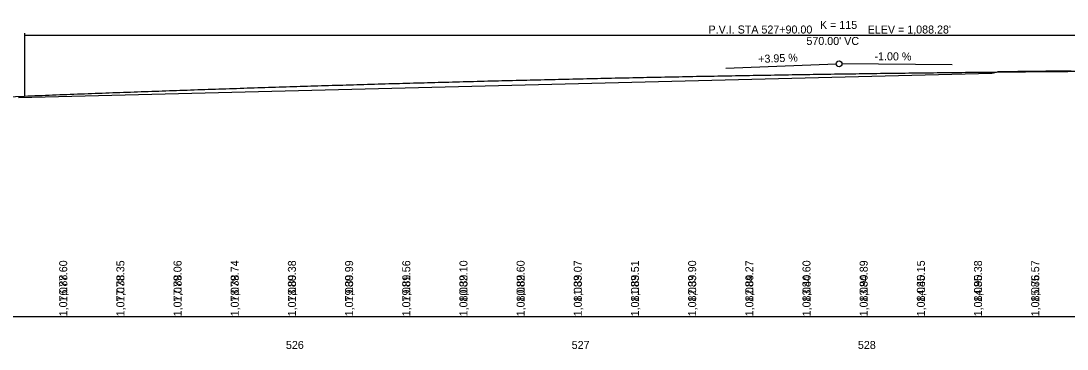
# Model space of a CAD drawing. Extents: x 2241514 to 2245530, y 509521 to 510188.
# Drawn here: x 2242780.9 to 2243146.9, y 509759.6 to 509874.3 of the extents above; entities that cross this region are included whole.
import ezdxf

# ---------------------------------------------------------------- set-up
doc = ezdxf.new("R2010")
doc.units = 0
for name, color, linetype in [('GK_Cells', 7, 'Continuous'), ('PF_P_Grade_Line', 7, 'Continuous'), ('PF_P_Sta_Elev_Text', 7, 'Continuous'), ('PF_P_Text', 7, 'Continuous'), ('PF_X_Ground_Line', 7, 'Continuous'), ('PF_X_Text', 7, 'Continuous')]:
    doc.layers.add(name, color=color, linetype=linetype)

msp = doc.modelspace()

# ---------------------------------------------------------------- linework, layer by layer
at = {"layer": 'GK_Cells'}
msp.add_line((2241529.6, 509771.03), (2245529.6, 509771.03), dxfattribs=at)
at = {"layer": 'PF_P_Grade_Line'}
msp.add_line((2242718.21, 509845.53), (2242782.14, 509848.05), dxfattribs=at)
msp.add_spline([(2242782.14, 509848.05), (2242792.04, 509848.44), (2242801.94, 509848.82), (2242811.84, 509849.19), (2242821.74, 509849.55), (2242831.64, 509849.9), (2242841.54, 509850.25), (2242851.44, 509850.58), (2242861.34, 509850.91), (2242871.24, 509851.23), (2242881.14, 509851.54), (2242891.04, 509851.84), (2242900.94, 509852.13), (2242910.84, 509852.42), (2242920.74, 509852.69), (2242930.64, 509852.96), (2242940.54, 509853.22), (2242950.44, 509853.47), (2242960.34, 509853.71), (2242970.24, 509853.95), (2242980.14, 509854.17), (2242990.04, 509854.39), (2242999.94, 509854.6), (2243009.84, 509854.8), (2243019.74, 509854.99), (2243029.64, 509855.17), (2243039.54, 509855.34), (2243049.44, 509855.51), (2243059.34, 509855.67), (2243069.24, 509855.82), (2243079.14, 509855.96), (2243089.04, 509856.09), (2243098.94, 509856.21), (2243108.84, 509856.32), (2243118.74, 509856.43), (2243128.64, 509856.53), (2243138.54, 509856.62), (2243148.44, 509856.7), (2243158.34, 509856.77), (2243168.24, 509856.83), (2243178.14, 509856.89), (2243188.04, 509856.93), (2243197.94, 509856.97), (2243207.84, 509857), (2243217.74, 509857.02), (2243227.64, 509857.03), (2243237.54, 509857.04), (2243247.44, 509857.03), (2243257.34, 509857.02), (2243267.24, 509857), (2243277.14, 509856.97)], degree=3, dxfattribs=at)
at = {"layer": 'PF_P_Text'}
for p, q in [((2242782.14, 509870.01), (2242782.14, 509848.05)), ((2242782.14, 509869.31), (2243277.14, 509869.31)), ((2243027.57, 509857.75), (2243066.14, 509859.27)), ((2243106.74, 509858.92), (2243068.14, 509859.3))]:
    msp.add_line(p, q, dxfattribs=at)
msp.add_circle((2243067.14, 509859.31), 1, dxfattribs=at)
at = {"layer": 'PF_X_Ground_Line'}
for points in [[(2242780.08, 509847.49), (2243120.52, 509856.02), (2243122.23, 509856.45), (2243122.77, 509856.59), (2243124.08, 509856.6), (2243124.84, 509856.61), (2243125.38, 509856.62), (2243127.02, 509856.64), (2243127.37, 509856.65)], [(2243127.37, 509856.65), (2243127.66, 509856.65), (2243127.94, 509856.66), (2243129.65, 509856.7), (2243130.76, 509856.72), (2243131.81, 509856.74), (2243133.16, 509856.77), (2243133.78, 509856.77), (2243134.98, 509856.77), (2243135, 509856.77), (2243135.97, 509856.79), (2243136.39, 509856.79), (2243138.28, 509856.8), (2243139.44, 509856.81), (2243140.48, 509856.82), (2243140.83, 509856.83), (2243142.08, 509856.84), (2243143.01, 509856.86), (2243143.91, 509856.87), (2243144.69, 509856.88), (2243145.85, 509856.9), (2243146.18, 509856.9), (2243146.43, 509856.9), (2243148.27, 509856.92)]]:
    msp.add_lwpolyline(points, dxfattribs=at)

# ---------------------------------------------------------------- texts
at = {"layer": 'PF_P_Sta_Elev_Text'}
for s, p in [('526', (2242873.65, 509759.63)), ('527', (2242973.6, 509759.63)), ('528', (2243073.72, 509759.63))]:
    msp.add_text(s, height=2.8, dxfattribs=at).set_placement(p)
at = {"layer": 'PF_P_Text'}
for s, p in [('P.V.I. STA 527+90.00', (2243021.46, 509869.91)), ('K = 115', (2243060.45, 509871.51)), ("ELEV = 1,088.28'", (2243077.14, 509869.91)), ("570.00' VC", (2243055.71, 509865.91))]:
    msp.add_text(s, height=2.8, dxfattribs=at).set_placement(p)
for s, rotation, p in [('+3.95 %', 2.262, (2243038.9, 509859.6)), ('-1.00 %', 359.4271, (2243079.51, 509860.59)), ('1,077.60', 90, (2242797.14, 509776.03)), ('1,078.35', 90, (2242817.14, 509776.03)), ('1,079.06', 90, (2242837.14, 509776.03)), ('1,079.74', 90, (2242857.14, 509776.03)), ('1,080.38', 90, (2242877.14, 509776.03)), ('1,080.99', 90, (2242897.14, 509776.03)), ('1,081.56', 90, (2242917.14, 509776.03)), ('1,082.10', 90, (2242937.14, 509776.03)), ('1,082.60', 90, (2242957.14, 509776.03)), ('1,083.07', 90, (2242977.14, 509776.03)), ('1,083.51', 90, (2242997.14, 509776.03)), ('1,083.90', 90, (2243017.14, 509776.03)), ('1,084.27', 90, (2243037.14, 509776.03)), ('1,084.60', 90, (2243057.14, 509776.03)), ('1,084.89', 90, (2243077.14, 509776.03)), ('1,085.15', 90, (2243097.14, 509776.03)), ('1,085.38', 90, (2243117.14, 509776.03)), ('1,085.57', 90, (2243137.14, 509776.03))]:
    msp.add_text(s, height=2.8, rotation=rotation, dxfattribs=at).set_placement(p)
at = {"layer": 'PF_X_Text'}
for s, p in [('1,076.88', (2242797.14, 509771.03)), ('1,077.38', (2242817.14, 509771.03)), ('1,077.88', (2242837.14, 509771.03)), ('1,078.38', (2242857.14, 509771.03)), ('1,078.89', (2242877.14, 509771.03)), ('1,079.39', (2242897.14, 509771.03)), ('1,079.89', (2242917.14, 509771.03)), ('1,080.39', (2242937.14, 509771.03)), ('1,080.89', (2242957.14, 509771.03)), ('1,081.39', (2242977.14, 509771.03)), ('1,081.89', (2242997.14, 509771.03)), ('1,082.39', (2243017.14, 509771.03)), ('1,082.89', (2243037.14, 509771.03)), ('1,083.40', (2243057.14, 509771.03)), ('1,083.90', (2243077.14, 509771.03)), ('1,084.40', (2243097.14, 509771.03)), ('1,084.90', (2243117.14, 509771.03)), ('1,085.76', (2243137.14, 509771.03))]:
    msp.add_text(s, height=2.8, rotation=90, dxfattribs=at).set_placement(p)

doc.saveas('drawing.dxf')
